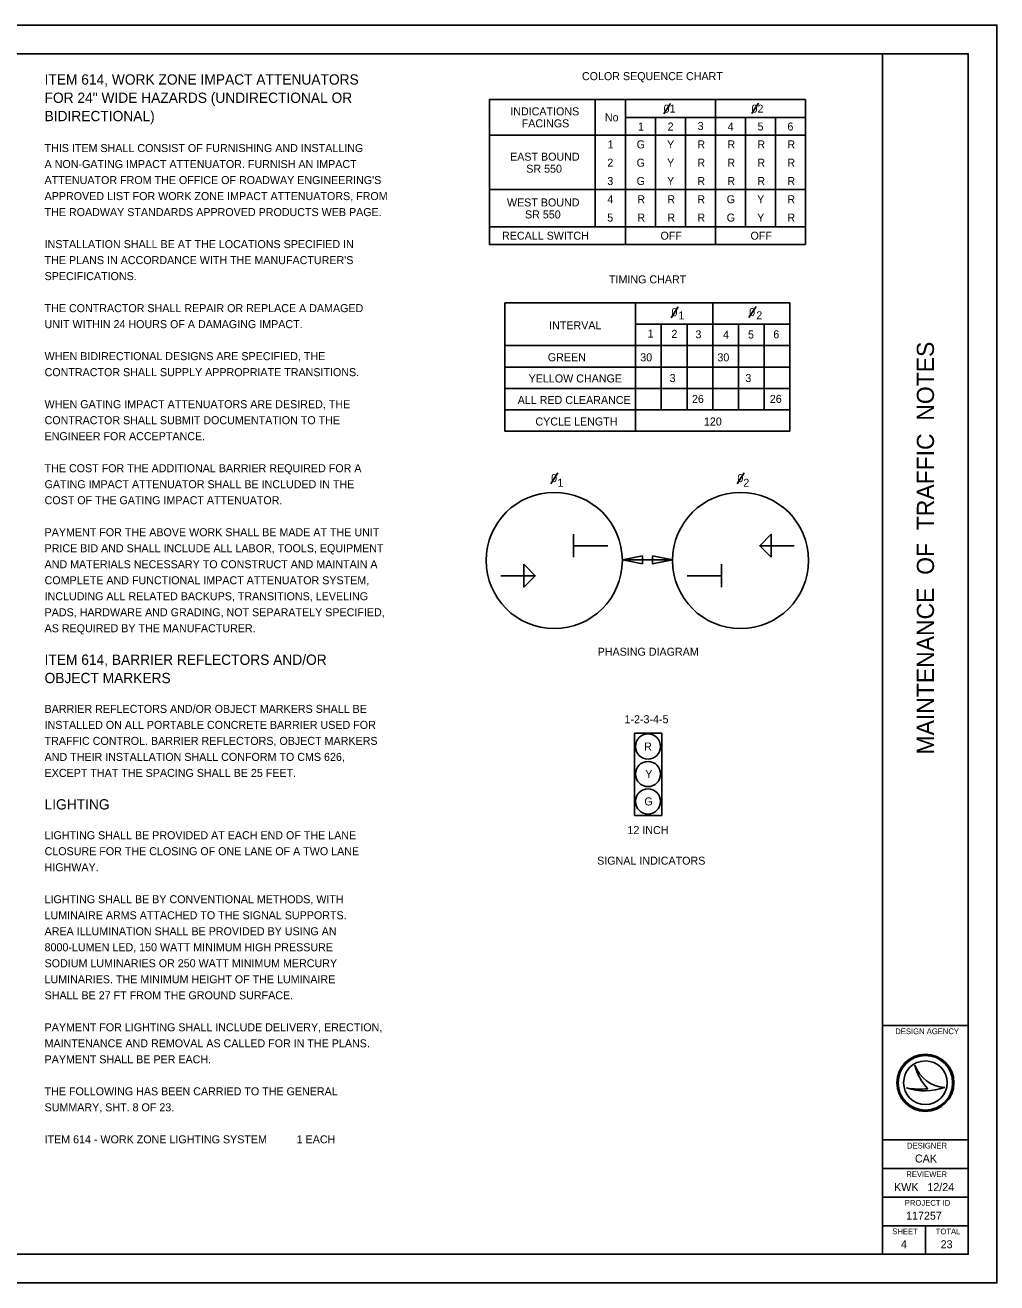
# Model space of a CAD drawing. Extents: x -37 to 104, y -26 to 49.
# Drawn here: x 17 to 34, y 0 to 22 of the extents above; entities that cross this region are included whole.
import ezdxf

# ---------------------------------------------------------------- set-up
doc = ezdxf.new("R2010")
doc.units = 0
for name, color, linetype in [('Default', 7, 'Continuous'), ('SG_P_Heads', 7, 'Continuous'), ('SH_Border', 7, 'Continuous'), ('SH_Cut_Line', 7, 'Continuous'), ('SH_Data', 7, 'Continuous'), ('SH_Text', 7, 'Continuous'), ('TX_P_1', 7, 'Continuous')]:
    doc.layers.add(name, color=color, linetype=linetype)

msp = doc.modelspace()

# ---------------------------------------------------------------- linework, layer by layer
at = {"layer": 'Default'}
for p, q in [((25.122, 20.699), (25.122, 18.162)), ((25.122, 20.699), (30.652, 20.699)), ((26.972, 20.699), (26.972, 18.474)), ((27.502, 20.699), (27.502, 18.162)), ((29.077, 20.699), (29.077, 18.162)), ((30.652, 20.699), (30.652, 18.512)), ((30.652, 20.699), (30.652, 18.162)), ((27.502, 20.387), (30.652, 20.387)), ((28.027, 20.387), (28.027, 18.474)), ((28.552, 20.387), (28.552, 18.474)), ((29.602, 20.387), (29.602, 18.474)), ((30.127, 20.387), (30.127, 18.474)), ((25.122, 20.074), (30.652, 20.074)), ((25.122, 19.127), (30.652, 19.127)), ((25.122, 18.474), (30.652, 18.474)), ((25.122, 18.162), (30.652, 18.162)), ((25.394, 17.145), (30.38, 17.145)), ((25.394, 17.145), (25.394, 14.895)), ((27.68, 17.145), (27.68, 14.895)), ((29.03, 17.145), (29.03, 15.27)), ((30.38, 17.145), (30.38, 14.895)), ((27.68, 16.77), (30.38, 16.77)), ((28.13, 16.77), (28.13, 15.27)), ((28.58, 16.77), (28.58, 15.27)), ((29.48, 16.77), (29.48, 15.27)), ((29.93, 16.77), (29.93, 15.27)), ((25.394, 16.395), (30.38, 16.395)), ((25.394, 16.02), (30.38, 16.02)), ((25.394, 15.645), (30.38, 15.645)), ((25.394, 15.27), (30.38, 15.27)), ((25.394, 14.895), (30.38, 14.895)), ((28.138, 9.617), (27.659, 9.617)), ((27.659, 9.617), (27.659, 8.175)), ((28.138, 8.175), (28.138, 9.617)), ((27.659, 8.175), (28.138, 8.175))]:
    msp.add_line(p, q, dxfattribs=at)
for centre in [(27.897, 9.381), (27.897, 8.9), (27.897, 8.421)]:
    msp.add_circle(centre, 0.22, dxfattribs=at)
at = {"layer": 'SG_P_Heads'}
for p, q in [((26.593, 13.096), (26.593, 12.696)), ((27.193, 12.895), (26.593, 12.895)), ((30.452, 12.895), (29.852, 12.895)), ((29.182, 12.17), (29.182, 12.57)), ((25.322, 12.37), (25.923, 12.37)), ((28.581, 12.37), (29.182, 12.37))]:
    msp.add_line(p, q, dxfattribs=at)
for points in [[(30.052, 12.695), (29.852, 12.895), (30.052, 13.095)], [(25.723, 12.57), (25.923, 12.37), (25.723, 12.17)], [(27.8, 12.575), (27.45, 12.645), (27.8, 12.715)], [(27.974, 12.715), (28.324, 12.645), (27.974, 12.575)]]:
    msp.add_lwpolyline(points, close=True, dxfattribs=at)
at = {"layer": 'SH_Border'}
for p, q in [((32, 0.5), (32, 21.5)), ((32, 4.5), (33.5, 4.5)), ((32, 2.5), (33.5, 2.5)), ((32, 2), (33.5, 2)), ((32, 1.5), (33.5, 1.5)), ((32, 1), (33.5, 1))]:
    msp.add_line(p, q, dxfattribs=at)
msp.add_lwpolyline([(1.5, 21.5), (33.5, 21.5), (33.5, 0.5), (1.5, 0.5)], close=True, dxfattribs=at)
at = {"layer": 'SH_Cut_Line'}
msp.add_lwpolyline([(0, 0), (34, 0), (34, 22), (0, 22)], close=True, dxfattribs=at)
at = {"layer": 'SH_Data'}
for p, q in [((28.324, 12.645), (27.45, 12.645)), ((32.567, 3.81), (32.567, 3.81)), ((32.417, 3.41), (32.417, 3.41)), ((32.75, 3.5), (32.75, 3.5)), ((33.087, 3.419), (33.087, 3.419)), ((32.75, 0.5), (32.75, 1)), ((32.375, 0.675), (32.375, 0.675))]:
    msp.add_line(p, q, dxfattribs=at)
for centre, radius in [((26.257, 12.636), 1.191), ((29.516, 12.636), 1.191), ((32.75, 3.5), 0.5), ((32.75, 3.5), 0.477), ((32.75, 3.5), 0.477), ((32.75, 3.5), 0.382)]:
    msp.add_circle(centre, radius, dxfattribs=at)
for centre, radius, start, end in [((33.116, 3.998), 0.58, 198.9257, 198.9319), ((33.347, 3.97), 0.796, 191.6379, 191.6421), ((33.116, 3.998), 0.58, 198.9319, 267.1657), ((33.347, 3.97), 0.796, 191.6421, 226.0947), ((32.739, 4.37), 1.013, 251.4576, 290.0832), ((32.648, 4.654), 1.266, 259.4964, 259.4995), ((32.739, 4.37), 1.013, 251.4527, 251.4576), ((32.648, 4.654), 1.266, 259.4995, 276.6672)]:
    msp.add_arc(centre, radius, start, end, dxfattribs=at)
at = {"layer": 'TX_P_1'}
for p, q in [((28.176, 20.45), (28.291, 20.631)), ((29.715, 20.456), (29.831, 20.637)), ((28.425, 17.074), (28.3, 16.882)), ((29.788, 17.078), (29.663, 16.885)), ((26.322, 14.169), (26.196, 13.977)), ((29.581, 14.169), (29.455, 13.977))]:
    msp.add_line(p, q, dxfattribs=at)

# ---------------------------------------------------------------- texts
at = {"layer": 'Default'}
for s, p in [('COLOR SEQUENCE CHART', (26.741, 21.038)), ('TIMING CHART', (27.214, 17.483)), ('R', (27.83, 9.311)), ('Y', (27.849, 8.831)), ('G', (27.833, 8.351)), ('SIGNAL INDICATORS', (27.007, 7.315))]:
    msp.add_text(s, height=0.14, dxfattribs=at).set_placement(p)
at = {"layer": 'SH_Data'}
msp.add_text('MAINTENANCE  OF  TRAFFIC  NOTES', height=0.3, rotation=90, dxfattribs=at).set_placement((32.9, 9.242))
for s, height, p in [('0', 0.14, (26.202, 14.007)), ('DESIGN AGENCY', 0.1, (32.223, 4.35)), ('DESIGNER', 0.1, (32.429, 2.35)), ('CAK', 0.14, (32.567, 2.105)), ('REVIEWER', 0.1, (32.416, 1.85)), ('KWK   12/24', 0.14, (32.202, 1.605)), ('PROJECT ID', 0.1, (32.39, 1.35)), ('117257', 0.14, (32.412, 1.105)), ('SHEET', 0.1, (32.17, 0.85)), ('TOTAL', 0.1, (32.931, 0.85)), ('4', 0.14, (32.323, 0.605)), ('23', 0.14, (33.017, 0.605))]:
    msp.add_text(s, height=height, dxfattribs=at).set_placement(p)
at = {"layer": 'SH_Text'}
for s, height, p in [('ITEM 614, WORK ZONE IMPACT ATTENUATORS', 0.18, (17.34, 20.96)), ('FOR 24" WIDE HAZARDS (UNDIRECTIONAL OR', 0.18, (17.34, 20.64)), ('BIDIRECTIONAL)', 0.18, (17.34, 20.32)), ('THIS ITEM SHALL CONSIST OF FURNISHING AND INSTALLING', 0.14, (17.34, 19.78)), ('A NON-GATING IMPACT ATTENUATOR. FURNISH AN IMPACT', 0.14, (17.34, 19.5)), ("ATTENUATOR FROM THE OFFICE OF ROADWAY ENGINEERING'S", 0.14, (17.34, 19.22)), ('APPROVED LIST FOR WORK ZONE IMPACT ATTENUATORS, FROM', 0.14, (17.34, 18.94)), ('THE ROADWAY STANDARDS APPROVED PRODUCTS WEB PAGE.', 0.14, (17.34, 18.66)), ('INSTALLATION SHALL BE AT THE LOCATIONS SPECIFIED IN', 0.14, (17.34, 18.1)), ("THE PLANS IN ACCORDANCE WITH THE MANUFACTURER'S", 0.14, (17.34, 17.82)), ('SPECIFICATIONS.', 0.14, (17.34, 17.54)), ('THE CONTRACTOR SHALL REPAIR OR REPLACE A DAMAGED', 0.14, (17.34, 16.98)), ('UNIT WITHIN 24 HOURS OF A DAMAGING IMPACT.', 0.14, (17.34, 16.7)), ('WHEN BIDIRECTIONAL DESIGNS ARE SPECIFIED, THE', 0.14, (17.34, 16.14)), ('CONTRACTOR SHALL SUPPLY APPROPRIATE TRANSITIONS.', 0.14, (17.34, 15.86)), ('WHEN GATING IMPACT ATTENUATORS ARE DESIRED, THE', 0.14, (17.34, 15.3)), ('CONTRACTOR SHALL SUBMIT DOCUMENTATION TO THE', 0.14, (17.34, 15.02)), ('ENGINEER FOR ACCEPTANCE.', 0.14, (17.34, 14.74)), ('THE COST FOR THE ADDITIONAL BARRIER REQUIRED FOR A', 0.14, (17.34, 14.18)), ('GATING IMPACT ATTENUATOR SHALL BE INCLUDED IN THE', 0.14, (17.34, 13.9)), ('COST OF THE GATING IMPACT ATTENUATOR.', 0.14, (17.34, 13.62)), ('PAYMENT FOR THE ABOVE WORK SHALL BE MADE AT THE UNIT', 0.14, (17.34, 13.06)), ('PRICE BID AND SHALL INCLUDE ALL LABOR, TOOLS, EQUIPMENT', 0.14, (17.34, 12.78)), ('AND MATERIALS NECESSARY TO CONSTRUCT AND MAINTAIN A', 0.14, (17.34, 12.5)), ('COMPLETE AND FUNCTIONAL IMPACT ATTENUATOR SYSTEM,', 0.14, (17.34, 12.22)), ('INCLUDING ALL RELATED BACKUPS, TRANSITIONS, LEVELING', 0.14, (17.34, 11.94)), ('PADS, HARDWARE AND GRADING, NOT SEPARATELY SPECIFIED,', 0.14, (17.34, 11.66)), ('AS REQUIRED BY THE MANUFACTURER.', 0.14, (17.34, 11.38)), ('ITEM 614, BARRIER REFLECTORS AND/OR', 0.18, (17.34, 10.81)), ('OBJECT MARKERS', 0.18, (17.34, 10.49)), ('BARRIER REFLECTORS AND/OR OBJECT MARKERS SHALL BE ', 0.14, (17.34, 9.97)), ('INSTALLED ON ALL PORTABLE CONCRETE BARRIER USED FOR ', 0.14, (17.34, 9.69)), ('TRAFFIC CONTROL. BARRIER REFLECTORS, OBJECT MARKERS', 0.14, (17.34, 9.41)), ('AND THEIR INSTALLATION SHALL CONFORM TO CMS 626,', 0.14, (17.34, 9.13)), ('EXCEPT THAT THE SPACING SHALL BE 25 FEET.', 0.14, (17.34, 8.85)), ('LIGHTING', 0.18, (17.34, 8.28)), ('LIGHTING SHALL BE PROVIDED AT EACH END OF THE LANE', 0.14, (17.34, 7.76)), ('CLOSURE FOR THE CLOSING OF ONE LANE OF A TWO LANE', 0.14, (17.34, 7.48)), ('HIGHWAY.', 0.14, (17.34, 7.2)), ('LIGHTING SHALL BE BY CONVENTIONAL METHODS, WITH', 0.14, (17.34, 6.64)), ('LUMINAIRE ARMS ATTACHED TO THE SIGNAL SUPPORTS.', 0.14, (17.34, 6.36)), ('AREA ILLUMINATION SHALL BE PROVIDED BY USING AN', 0.14, (17.34, 6.08)), ('8000-LUMEN LED, 150 WATT MINIMUM HIGH PRESSURE', 0.14, (17.34, 5.8)), ('SODIUM LUMINARIES OR 250 WATT MINIMUM MERCURY', 0.14, (17.34, 5.52)), ('LUMINARIES. THE MINIMUM HEIGHT OF THE LUMINAIRE', 0.14, (17.34, 5.24)), ('SHALL BE 27 FT FROM THE GROUND SURFACE.', 0.14, (17.34, 4.96)), ('PAYMENT FOR LIGHTING SHALL INCLUDE DELIVERY, ERECTION,', 0.14, (17.34, 4.4)), ('MAINTENANCE AND REMOVAL AS CALLED FOR IN THE PLANS.', 0.14, (17.34, 4.12)), ('PAYMENT SHALL BE PER EACH.', 0.14, (17.34, 3.84)), ('THE FOLLOWING HAS BEEN CARRIED TO THE GENERAL', 0.14, (17.34, 3.28)), ('SUMMARY, SHT. 8 OF 23.', 0.14, (17.34, 3)), ('ITEM 614 - WORK ZONE LIGHTING SYSTEM          1 EACH', 0.14, (17.34, 2.44))]:
    msp.add_text(s, height=height, dxfattribs=at).set_placement(p)
at = {"layer": 'TX_P_1'}
for s, p in [('INDICATIONS', (25.487, 20.422)), ('01', (28.17, 20.469)), ('02', (29.708, 20.469)), ('FACINGS', (25.687, 20.212)), ('No', (27.143, 20.317)), ('1', (27.721, 20.157)), ('2', (28.24, 20.157)), ('3', (28.765, 20.167)), ('4', (29.29, 20.157)), ('5', (29.814, 20.157)), ('6', (30.336, 20.157)), ('1', (27.191, 19.844)), ('G', (27.698, 19.844)), ('Y', (28.231, 19.844)), ('R', (28.76, 19.844)), ('R', (29.285, 19.844)), ('R', (29.81, 19.844)), ('R', (30.335, 19.844)), ('EAST BOUND', (25.484, 19.629)), ('2', (27.185, 19.524)), ('G', (27.698, 19.524)), ('Y', (28.231, 19.524)), ('R', (28.76, 19.524)), ('R', (29.285, 19.524)), ('R', (29.81, 19.524)), ('R', (30.335, 19.524)), ('SR 550', (25.767, 19.419)), ('3', (27.185, 19.204)), ('G', (27.698, 19.204)), ('Y', (28.231, 19.204)), ('R', (28.76, 19.204)), ('R', (29.285, 19.204)), ('R', (29.81, 19.204)), ('R', (30.335, 19.204)), ('WEST BOUND', (25.429, 18.829)), ('4', (27.185, 18.884)), ('R', (27.71, 18.884)), ('R', (28.235, 18.884)), ('R', (28.76, 18.884)), ('G', (29.273, 18.884)), ('Y', (29.806, 18.884)), ('R', (30.335, 18.884)), ('SR 550', (25.745, 18.619)), ('5', (27.184, 18.564)), ('R', (27.71, 18.564)), ('R', (28.235, 18.564)), ('R', (28.76, 18.564)), ('G', (29.273, 18.564)), ('Y', (29.806, 18.564)), ('R', (30.335, 18.564)), ('RECALL SWITCH', (25.343, 18.247)), ('OFF', (28.115, 18.247)), ('OFF', (29.69, 18.247)), ('0', (28.307, 16.908)), ('1', (28.429, 16.852)), ('0', (29.666, 16.911)), ('2', (29.791, 16.855)), ('INTERVAL ', (26.167, 16.679)), ('1', (27.889, 16.533)), ('2', (28.306, 16.53)), ('3', (28.727, 16.521)), ('4', (29.21, 16.517)), ('5', (29.647, 16.519)), ('6', (30.089, 16.522)), (' GREEN', (26.092, 16.121)), ('30', (27.761, 16.119)), ('30', (29.111, 16.119)), ('YELLOW CHANGE', (25.809, 15.75)), ('3', (28.275, 15.757)), ('3', (29.6, 15.757)), ('ALL RED CLEARANCE', (25.617, 15.373)), ('26', (28.666, 15.392)), ('26', (30.028, 15.392)), ('CYCLE LENGTH', (25.927, 14.997)), ('120', (28.875, 14.997)), ('0', (29.461, 14.007)), ('1', (26.312, 13.926)), ('2', (29.565, 13.926)), ('PHASING DIAGRAM', (27.016, 10.97)), ('1-2-3-4-5', (27.486, 9.789)), ('12 INCH', (27.537, 7.85))]:
    msp.add_text(s, height=0.14, dxfattribs=at).set_placement(p)

doc.saveas('drawing.dxf')
